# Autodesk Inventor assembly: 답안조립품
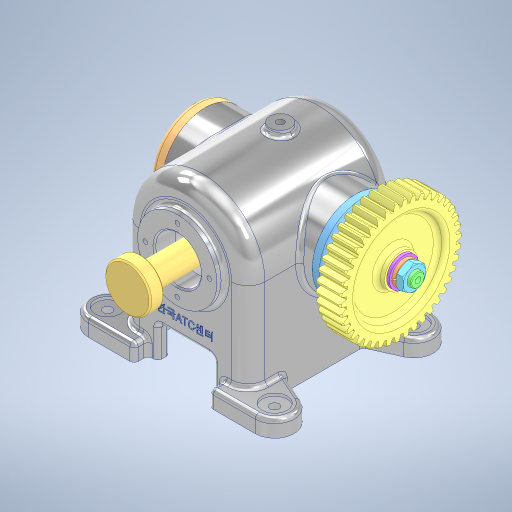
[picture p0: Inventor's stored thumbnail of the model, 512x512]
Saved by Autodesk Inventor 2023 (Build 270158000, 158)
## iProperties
Created: 2024-09
Part Number: 답안조립품
Document SubType Name: Assembly
Designer: asung
Author: asung
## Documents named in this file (14)
- C:\Users\asung\Desktop\740904V1003\답안조립품.iam
- C:\Users\asung\Desktop\740904V1003\본체.ipt
- C:\Users\asung\Desktop\740904V1003\뒷커버.ipt
- C:\Users\asung\Desktop\740904V1003\깊은 홈 볼베어링 6203.ipt
- C:\Users\asung\Desktop\740904V1003\편심축.ipt
- C:\Users\asung\Desktop\740904V1003\평행키 3x3x14.ipt
- C:\Users\asung\Desktop\740904V1003\로드.ipt
- C:\Users\asung\Desktop\740904V1003\앞커버.ipt
- C:\Users\asung\Desktop\740904V1003\오일실 17 32 8.ipt
- C:\Users\asung\Desktop\740904V1003\육각 소켓 머리 볼트 M4x10.ipt
- C:\Users\asung\Desktop\740904V1003\스퍼 기어.ipt
- C:\Users\asung\Desktop\740904V1003\평와셔 M10.ipt
- C:\Users\asung\Desktop\740904V1003\스프링와셔 M10.ipt
- C:\Users\asung\Desktop\740904V1003\육각 너트 M10x1.ipt
